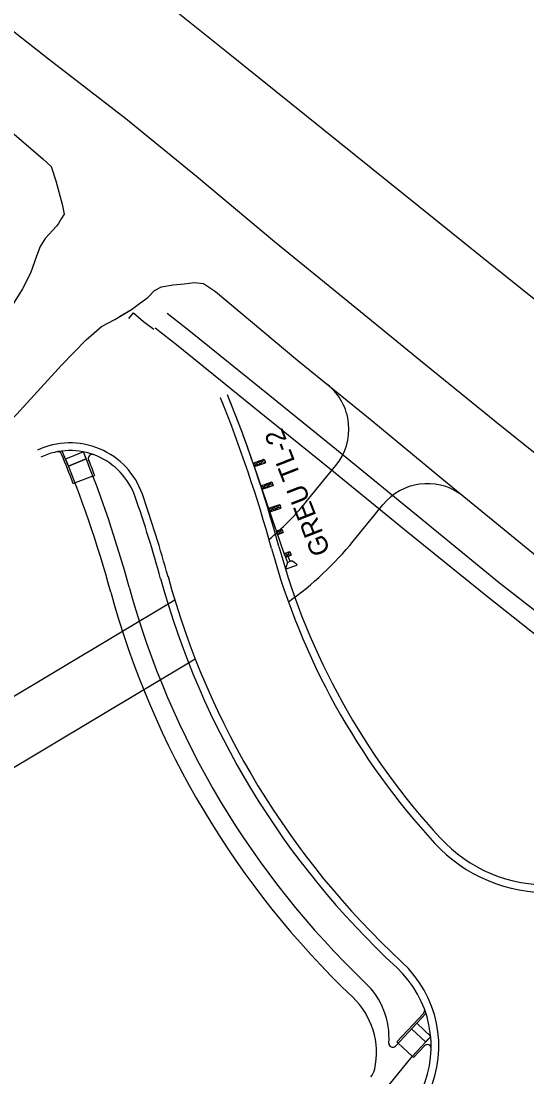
# Model space of a CAD drawing. Extents: x 1487693 to 1489338, y 497936 to 499734.
# Drawn here: x 1488564.2 to 1488696.3, y 499075 to 499350.8 of the extents above; entities that cross this region are included whole.
import ezdxf

# ---------------------------------------------------------------- set-up
doc = ezdxf.new("R2010")
doc.units = 0
for name, color, linetype in [('Exist Railroads Standard Gauge', 7, 'Continuous'), ('Exist Roads Curbs', 7, 'Continuous'), ('Exist Roads EOP', 7, 'Continuous'), ('Exist Roads EOP Other', 7, 'Continuous'), ('Pattern 5', 7, 'Continuous'), ('Prop Conc 1ft 6in Curb and Gutter', 7, 'Continuous'), ('Prop Conc 2ft 6in Curb and Gutter', 7, 'Continuous'), ('Prop Conc 4in Sidewalk', 7, 'Continuous'), ('Prop EOT', 7, 'Continuous'), ('Prop Guardrail', 7, 'Continuous'), ('Prop Guardrail Anchor Unit CELL', 7, 'Continuous')]:
    doc.layers.add(name, color=color, linetype=linetype)

msp = doc.modelspace()

# ---------------------------------------------------------------- linework, layer by layer
at = {"layer": 'Exist Railroads Standard Gauge'}
msp.add_lwpolyline([(1488972.75, 499057.15), (1488947.35, 499077.62), (1488919.48, 499100.08), (1488890.07, 499123.82), (1488841.68, 499162.79), (1488822.88, 499177.94), (1488795.51, 499200.11), (1488763.62, 499225.91), (1488727.57, 499254.8), (1488692.17, 499283.06), (1488664.12, 499305.6), (1488617.82, 499342.84), (1488599.16, 499357.84), (1488532.76, 499411.39), (1488485.03, 499449.93), (1488450.03, 499478.08), (1488423.37, 499499.63), (1488397.39, 499520.51), (1488361.21, 499549.74)], dxfattribs=at)
at = {"layer": 'Exist Roads Curbs'}
msp.add_lwpolyline([(1488592.32, 499273.13), (1488593.53, 499274.58), (1488596.18, 499272.39), (1488598.88, 499270.39)], dxfattribs=at)
at = {"layer": 'Exist Roads EOP'}
for points in [[(1488316.71, 499516.76), (1488322.91, 499511.87), (1488362.48, 499480.8), (1488401.61, 499449.34), (1488441.42, 499418.39), (1488480.75, 499387.27), (1488519.83, 499355.62), (1488558.68, 499324.4), (1488569.9, 499314.83), (1488572.03, 499312.84), (1488573.24, 499309.12), (1488574.89, 499302.98), (1488575.47, 499300.42), (1488574.66, 499299.19)], [(1488492.34, 499402.94), (1488510.18, 499389.27), (1488532.03, 499372.11), (1488553.67, 499354.78), (1488571.39, 499340.97), (1488591.6, 499325.39), (1488610.04, 499310.33), (1488630.4, 499293.26), (1488648.61, 499278.49), (1488668.5, 499262.14), (1488687.96, 499246.41), (1488710.36, 499228.49), (1488725.99, 499215.74), (1488744.07, 499202.68), (1488764.57, 499190.5), (1488781.13, 499183.98), (1488791.01, 499181.73), (1488798, 499181.14)], [(1488574.66, 499299.19), (1488573.94, 499297.98), (1488573.41, 499297.25), (1488570.49, 499294.07), (1488569.18, 499291.91), (1488568.27, 499289.4), (1488566.68, 499284.95), (1488564.58, 499280.92), (1488559.94, 499273.47)], [(1488574.77, 499260.93), (1488581.17, 499267.55), (1488585.21, 499271.08), (1488588.71, 499272.92), (1488593.01, 499275.5), (1488595.13, 499277.04), (1488597.32, 499278.66), (1488599.07, 499280.42), (1488600.85, 499281.4), (1488603.93, 499281.97), (1488606.78, 499282.21), (1488609.38, 499282.54), (1488611.82, 499282.27), (1488614.97, 499280.23), (1488636.47, 499262.18), (1488655.78, 499246.53), (1488675.03, 499230.53), (1488696.14, 499213.29), (1488713.83, 499198.84)], [(1488589.95, 499273.67), (1488593.01, 499275.5), (1488595.13, 499277.04), (1488597.32, 499278.66), (1488599.07, 499280.42), (1488600.85, 499281.4), (1488603.93, 499281.97), (1488606.78, 499282.21), (1488609.38, 499282.54), (1488611.82, 499282.27), (1488614.97, 499280.23), (1488636.47, 499262.18), (1488655.78, 499246.53), (1488675.03, 499230.53), (1488696.14, 499213.29), (1488713.83, 499198.84), (1488732.27, 499185.48), (1488744.49, 499177.32)], [(1488574.77, 499260.93), (1488563.13, 499248.19), (1488539.56, 499225.13), (1488520.46, 499206.56), (1488504.08, 499189.42), (1488484.54, 499170.35), (1488469.06, 499154.33), (1488450.55, 499135.83), (1488433.88, 499117.95), (1488414.86, 499097.38), (1488400.17, 499080.83), (1488378.14, 499057.25)]]:
    msp.add_lwpolyline(points, dxfattribs=at)
at = {"layer": 'Exist Roads EOP Other'}
for points in [[(1488602.38, 499274.53), (1488608.06, 499270.1), (1488629.14, 499252.99), (1488648.44, 499237.44), (1488667.92, 499221.49), (1488689.16, 499204.08), (1488707.19, 499190.07), (1488725.25, 499175.8), (1488730.15, 499171.85), (1488749.18, 499159.85), (1488759.05, 499153.7), (1488764.45, 499150.32), (1488767.65, 499149.49), (1488770.84, 499149.71), (1488775.38, 499150.61), (1488779.99, 499151.86), (1488784.82, 499153.57), (1488792.33, 499157.6)], [(1488599.22, 499270.73), (1488605.27, 499265.99), (1488625.52, 499249.58), (1488645.32, 499233.59), (1488664.77, 499217.66), (1488686.01, 499200.52), (1488704.08, 499186.22), (1488722.15, 499172.12), (1488725.54, 499169.27), (1488746.28, 499156.02), (1488755.98, 499150.14), (1488761.69, 499146.23), (1488766.7, 499144.8), (1488771.29, 499144.83), (1488776.64, 499145.87), (1488781.49, 499147.22), (1488786.93, 499149.39), (1488794.93, 499153.28), (1488801.06, 499156.82), (1488801.57, 499157.58)]]:
    msp.add_lwpolyline(points, dxfattribs=at)
at = {"layer": 'Pattern 5'}
for p, q in [((1488580.47, 499238.3), (1488575.84, 499236.41)), ((1488581.22, 499236.45), (1488580.47, 499238.3)), ((1488575.84, 499236.41), (1488576.59, 499234.56)), ((1488576.59, 499234.56), (1488581.22, 499236.45)), ((1488667.55, 499089.02), (1488666.18, 499087.56)), ((1488671.2, 499085.62), (1488667.55, 499089.02)), ((1488666.18, 499087.56), (1488669.83, 499084.15)), ((1488669.83, 499084.15), (1488671.2, 499085.62))]:
    msp.add_line(p, q, dxfattribs=at)
for points in [[(1488581.22, 499236.45), (1488581.22, 499236.45)], [(1488669.83, 499084.15), (1488669.83, 499084.15)]]:
    msp.add_lwpolyline(points, dxfattribs=at)
at = {"layer": 'Prop Conc 1ft 6in Curb and Gutter'}
for p, q in [((1488578.3, 499230.17), (1488577.84, 499229.99)), ((1488582.98, 499231.95), (1488583.44, 499232.12)), ((1488662.32, 499084.15), (1488669.37, 499091.71)), ((1488662.68, 499083.81), (1488662.32, 499084.15)), ((1488666.7, 499080.06), (1488669.58, 499083.15)), ((1488666.33, 499080.4), (1488666.7, 499080.06))]:
    msp.add_line(p, q, dxfattribs=at)
for centre, radius, start, end in [((1488573.83, 499237.34), 1, 22.4839, 100.7387), ((1488292.94, 499121.08), 305, 20.92, 22.4839), ((1488582.76, 499236.63), 1, 70.2165, 201.7376), ((1488292.94, 499121.08), 311, 20.9189, 21.7376), ((1488668.64, 499092.39), 1, 316.995, 20.3225), ((1488670.31, 499082.47), 1, 358.8535, 136.9971)]:
    msp.add_arc(centre, radius, start, end, dxfattribs=at)
at = {"layer": 'Prop Conc 2ft 6in Curb and Gutter'}
for centre, radius, start, end in [((1488292.94, 499121.08), 351, 15.2846, 22.1132), ((1488577, 499220.64), 18, 19.3141, 115.2255), ((1488292.94, 499121.08), 319, 15.2846, 19.3141), ((1488809.02, 499262.12), 184, 195.2846, 222.6475), ((1488809.02, 499262.12), 216, 195.2846, 227.2261), ((1488701.63, 499163.2), 38, 222.6475, 321.1156), ((1488643.32, 499083.01), 28, 336.027, 47.2261)]:
    msp.add_arc(centre, radius, start, end, dxfattribs=at)
at = {"layer": 'Prop Conc 4in Sidewalk'}
for p, q in [((1488580.47, 499238.3), (1488575.84, 499236.41)), ((1488581.22, 499236.45), (1488576.59, 499234.56)), ((1488582.98, 499231.95), (1488578.3, 499230.17)), ((1488662, 499083.08), (1488669.96, 499091.61)), ((1488671.2, 499085.62), (1488667.55, 499089.02)), ((1488669.83, 499084.15), (1488666.18, 499087.56)), ((1488666.33, 499080.4), (1488662.68, 499083.81)), ((1488666.32, 499080.39), (1488671.2, 499085.62)), ((1488627.75, 499032.57), (1488666.32, 499080.39))]:
    msp.add_line(p, q, dxfattribs=at)
for centre, radius, start, end in [((1488292.94, 499121.08), 305.5, 15.2846, 22.6075), ((1488292.94, 499121.08), 310.5, 15.2846, 22.1798), ((1488809.02, 499262.12), 224.5, 195.2846, 226.3706), ((1488809.02, 499262.12), 229.5, 195.2846, 226.422), ((1488640.32, 499085.14), 20, 356.2177, 46.3706), ((1488637.03, 499081.37), 20, 347.6839, 46.422), ((1488661.27, 499083.76), 1, 176.2177, 316.995), ((1488651.68, 499078.17), 5, 321.1156, 347.6839)]:
    msp.add_arc(centre, radius, start, end, dxfattribs=at)
at = {"layer": 'Prop EOT'}
for p, q in [((1488638.58, 499225.12), (1488646.43, 499234.72)), ((1488650.97, 499214.99), (1488658.73, 499224.49)), ((1488493.63, 499133.56), (1488604.33, 499199.66)), ((1488501.83, 499119.82), (1488609.7, 499184.23))]:
    msp.add_line(p, q, dxfattribs=at)
for centre, radius, start, end in [((1488634.82, 499244.21), 15, 320.7375, 50.9704), ((1488292.94, 499121.08), 349, 15.2846, 22.1132), ((1488577, 499220.64), 20, 19.3141, 115.2255), ((1488670.35, 499214.99), 15, 55.0649, 140.7375), ((1488292.94, 499121.08), 321, 15.2846, 19.3141), ((1488582.84, 499270.69), 72, 309.8335, 320.7375), ((1488809.02, 499262.12), 186, 195.2846, 222.6475), ((1488582.84, 499270.69), 88, 305.5637, 320.7375), ((1488809.02, 499262.12), 214, 195.2846, 227.2261), ((1488701.63, 499163.2), 40, 222.6475, 321.1156), ((1488643.32, 499083.01), 30, 336.027, 47.2261)]:
    msp.add_arc(centre, radius, start, end, dxfattribs=at)
at = {"layer": 'Prop Guardrail'}
msp.add_arc((1488292.94, 499121.08), 351, 19.0041, 22.1132, dxfattribs=at)
at = {"layer": 'Prop Guardrail Anchor Unit CELL'}
for p, q in [((1488624.81, 499235.38), (1488627.68, 499236.37)), ((1488624.81, 499235.38), (1488625.14, 499234.44)), ((1488624.81, 499235.38), (1488626.57, 499234.93)), ((1488626.25, 499235.88), (1488625.14, 499234.44)), ((1488625.14, 499234.44), (1488628.01, 499235.42)), ((1488626.25, 499235.88), (1488626.57, 499234.93)), ((1488628.01, 499235.42), (1488626.25, 499235.88)), ((1488626.57, 499234.93), (1488627.68, 499236.37)), ((1488627.68, 499236.37), (1488628.01, 499235.42)), ((1488633.12, 499211.27), (1488624.97, 499234.91)), ((1488626.85, 499229.47), (1488629.72, 499230.46)), ((1488626.85, 499229.47), (1488627.17, 499228.53)), ((1488626.85, 499229.47), (1488628.61, 499229.02)), ((1488628.28, 499229.97), (1488627.17, 499228.53)), ((1488627.17, 499228.53), (1488630.04, 499229.52)), ((1488628.28, 499229.97), (1488628.61, 499229.02)), ((1488630.04, 499229.52), (1488628.28, 499229.97)), ((1488628.61, 499229.02), (1488629.72, 499230.46)), ((1488629.72, 499230.46), (1488630.04, 499229.52)), ((1488628.88, 499223.56), (1488631.75, 499224.55)), ((1488630.32, 499224.06), (1488629.21, 499222.62)), ((1488630.32, 499224.06), (1488630.64, 499223.11)), ((1488632.08, 499223.61), (1488630.32, 499224.06)), ((1488630.64, 499223.11), (1488631.75, 499224.55)), ((1488631.75, 499224.55), (1488632.08, 499223.61)), ((1488628.88, 499223.56), (1488629.21, 499222.62)), ((1488628.88, 499223.56), (1488630.64, 499223.11)), ((1488629.21, 499222.62), (1488632.08, 499223.61)), ((1488630.92, 499217.65), (1488632.35, 499218.15)), ((1488630.92, 499217.65), (1488631.24, 499216.71)), ((1488630.92, 499217.65), (1488632.68, 499217.2)), ((1488632.35, 499218.15), (1488631.24, 499216.71)), ((1488631.24, 499216.71), (1488632.68, 499217.2)), ((1488632.35, 499218.15), (1488632.68, 499217.2)), ((1488632.96, 499211.74), (1488634.39, 499212.24)), ((1488632.96, 499211.74), (1488633.28, 499210.8)), ((1488632.96, 499211.74), (1488634.72, 499211.29)), ((1488634.39, 499212.24), (1488633.28, 499210.8)), ((1488633.28, 499210.8), (1488634.72, 499211.29)), ((1488633.29, 499210.8), (1488633.77, 499209.41)), ((1488634.45, 499209.65), (1488633.97, 499211.04)), ((1488634.39, 499212.24), (1488634.72, 499211.29)), ((1488633.77, 499209.41), (1488633.34, 499208.02)), ((1488633.34, 499208.02), (1488633.44, 499207.73)), ((1488633.44, 499207.73), (1488636.22, 499208.69)), ((1488634.93, 499209.81), (1488633.77, 499209.41)), ((1488636.12, 499208.98), (1488634.93, 499209.81)), ((1488636.12, 499208.98), (1488636.22, 499208.69))]:
    msp.add_line(p, q, dxfattribs=at)

# ---------------------------------------------------------------- texts
msp.add_text('GREU TL-2', height=5, rotation=111.3982, dxfattribs=at).set_placement((1488645.06, 499212.3))

doc.saveas('drawing.dxf')
